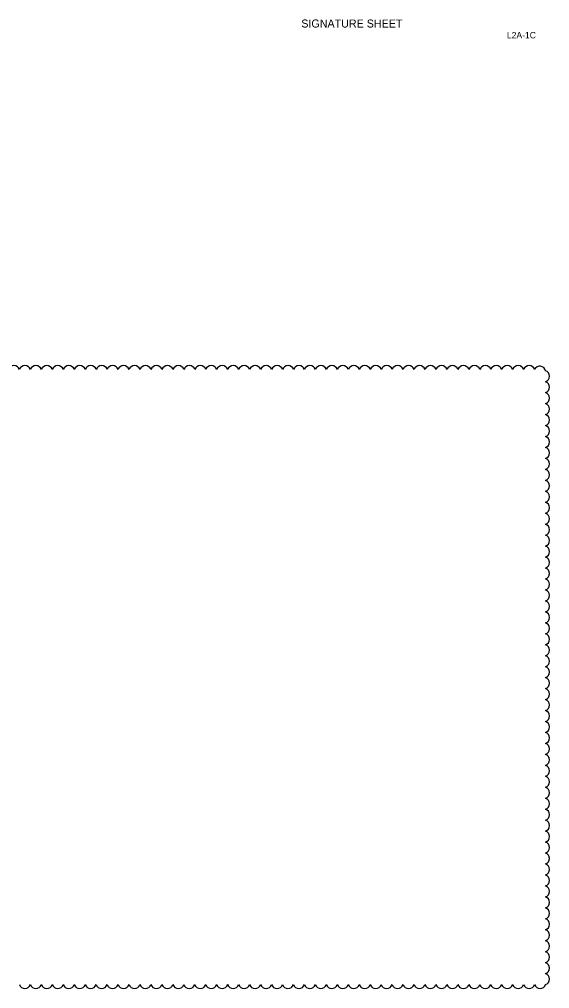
# Model space of a CAD drawing. Extents: x -811 to 10319, y -2309 to 9962.
# Drawn here: x -803.6 to -795.32, y -2244.74 to -2229.61 of the extents above; entities that cross this region are included whole.
import ezdxf

# ---------------------------------------------------------------- set-up
doc = ezdxf.new("R2010")
doc.units = 0
for name, color, linetype in [('PlotBorder_dp', 7, 'Continuous'), ('SheetLines_dp', 7, 'Continuous'), ('TextTitle', 7, 'Continuous')]:
    doc.layers.add(name, color=color, linetype=linetype)

msp = doc.modelspace()

# ---------------------------------------------------------------- linework, layer by layer
at = {"layer": 'TextTitle'}
for centre, radius, start, end in [((-803.684, -2235.106), 0.0897, 17.5, 162.5), ((-803.513, -2235.106), 0.0897, 17.5, 162.5), ((-803.342, -2235.106), 0.0897, 17.5, 162.5), ((-803.171, -2235.106), 0.0897, 17.5, 162.5), ((-803, -2235.106), 0.0897, 17.5, 162.5), ((-802.829, -2235.106), 0.0897, 17.5, 162.5), ((-802.657, -2235.106), 0.0897, 17.5, 162.5), ((-802.486, -2235.106), 0.0897, 17.5, 162.5), ((-802.315, -2235.106), 0.0897, 17.5, 162.5), ((-802.144, -2235.106), 0.0897, 17.5, 162.5), ((-801.973, -2235.106), 0.0897, 17.5, 162.5), ((-801.802, -2235.106), 0.0897, 17.5, 162.5), ((-801.631, -2235.106), 0.0897, 17.5, 162.5), ((-801.46, -2235.106), 0.0897, 17.5, 162.5), ((-801.288, -2235.106), 0.0897, 17.5, 162.5), ((-801.117, -2235.106), 0.0897, 17.5, 162.5), ((-800.946, -2235.106), 0.0897, 17.5, 162.5), ((-800.775, -2235.106), 0.0897, 17.5, 162.5), ((-800.604, -2235.106), 0.0897, 17.5, 162.5), ((-800.433, -2235.106), 0.0897, 17.5, 162.5), ((-800.262, -2235.106), 0.0897, 17.5, 162.5), ((-800.091, -2235.106), 0.0897, 17.5, 162.5), ((-799.919, -2235.106), 0.0897, 17.5, 162.5), ((-799.748, -2235.106), 0.0897, 17.5, 162.5), ((-799.577, -2235.106), 0.0897, 17.5, 162.5), ((-799.406, -2235.106), 0.0897, 17.5, 162.5), ((-799.235, -2235.106), 0.0897, 17.5, 162.5), ((-799.064, -2235.106), 0.0897, 17.5, 162.5), ((-798.893, -2235.106), 0.0897, 17.5, 162.5), ((-798.722, -2235.106), 0.0897, 17.5, 162.5), ((-798.551, -2235.106), 0.0897, 17.5, 162.5), ((-798.379, -2235.106), 0.0897, 17.5, 162.5), ((-798.208, -2235.106), 0.0897, 17.5, 162.5), ((-798.037, -2235.106), 0.0897, 17.5, 162.5), ((-797.866, -2235.106), 0.0897, 17.5, 162.5), ((-797.695, -2235.106), 0.0897, 17.5, 162.5), ((-797.524, -2235.106), 0.0897, 17.5, 162.5), ((-797.353, -2235.106), 0.0897, 17.5, 162.5), ((-797.182, -2235.106), 0.0897, 17.5, 162.5), ((-797.01, -2235.106), 0.0897, 17.5, 162.5), ((-796.839, -2235.106), 0.0897, 17.5, 162.5), ((-796.668, -2235.106), 0.0897, 17.5, 162.5), ((-796.497, -2235.106), 0.0897, 17.5, 162.5), ((-796.326, -2235.106), 0.0897, 17.5, 162.5), ((-796.155, -2235.106), 0.0897, 17.5, 162.5), ((-795.984, -2235.106), 0.0897, 17.5, 162.5), ((-795.813, -2235.106), 0.0897, 17.5, 162.5), ((-795.641, -2235.106), 0.0897, 17.5, 162.5), ((-795.474, -2235.115), 0.0896, 11.7454, 156.7454), ((-795.413, -2235.182), 0.0897, 287.5, 72.5), ((-795.413, -2235.353), 0.0897, 287.5, 72.5), ((-795.413, -2235.524), 0.0897, 287.5, 72.5), ((-795.413, -2235.695), 0.0897, 287.5, 72.5), ((-795.413, -2235.866), 0.0897, 287.5, 72.5), ((-795.413, -2236.038), 0.0897, 287.5, 72.5), ((-795.413, -2236.209), 0.0897, 287.5, 72.5), ((-795.413, -2236.38), 0.0897, 287.5, 72.5), ((-795.413, -2236.551), 0.0897, 287.5, 72.5), ((-795.413, -2236.722), 0.0897, 287.5, 72.5), ((-795.413, -2236.893), 0.0897, 287.5, 72.5), ((-795.413, -2237.064), 0.0897, 287.5, 72.5), ((-795.413, -2237.235), 0.0897, 287.5, 72.5), ((-795.413, -2237.407), 0.0897, 287.5, 72.5), ((-795.413, -2237.578), 0.0897, 287.5, 72.5), ((-795.413, -2237.749), 0.0897, 287.5, 72.5), ((-795.413, -2237.92), 0.0897, 287.5, 72.5), ((-795.413, -2238.091), 0.0897, 287.5, 72.5), ((-795.413, -2238.262), 0.0897, 287.5, 72.5), ((-795.413, -2238.433), 0.0897, 287.5, 72.5), ((-795.413, -2238.604), 0.0897, 287.5, 72.5), ((-795.413, -2238.776), 0.0897, 287.5, 72.5), ((-795.413, -2238.947), 0.0897, 287.5, 72.5), ((-795.413, -2239.118), 0.0897, 287.5, 72.5), ((-795.413, -2239.289), 0.0897, 287.5, 72.5), ((-795.413, -2239.46), 0.0897, 287.5, 72.5), ((-795.413, -2239.631), 0.0897, 287.5, 72.5), ((-795.413, -2239.802), 0.0897, 287.5, 72.5), ((-795.413, -2239.973), 0.0897, 287.5, 72.5), ((-795.413, -2240.144), 0.0897, 287.5, 72.5), ((-795.413, -2240.316), 0.0897, 287.5, 72.5), ((-795.413, -2240.487), 0.0897, 287.5, 72.5), ((-795.413, -2240.658), 0.0897, 287.5, 72.5), ((-795.413, -2240.829), 0.0897, 287.5, 72.5), ((-795.413, -2241), 0.0897, 287.5, 72.5), ((-795.413, -2241.171), 0.0897, 287.5, 72.5), ((-795.413, -2241.342), 0.0897, 287.5, 72.5), ((-795.413, -2241.513), 0.0897, 287.5, 72.5), ((-795.413, -2241.685), 0.0897, 287.5, 72.5), ((-795.413, -2241.856), 0.0897, 287.5, 72.5), ((-795.413, -2242.027), 0.0897, 287.5, 72.5), ((-795.413, -2242.198), 0.0897, 287.5, 72.5), ((-795.413, -2242.369), 0.0897, 287.5, 72.5), ((-795.413, -2242.54), 0.0897, 287.5, 72.5), ((-795.413, -2242.711), 0.0897, 287.5, 72.5), ((-795.413, -2242.882), 0.0897, 287.5, 72.5), ((-795.413, -2243.054), 0.0897, 287.5, 72.5), ((-795.413, -2243.225), 0.0897, 287.5, 72.5), ((-795.413, -2243.396), 0.0897, 287.5, 72.5), ((-795.413, -2243.567), 0.0897, 287.5, 72.5), ((-795.413, -2243.738), 0.0897, 287.5, 72.5), ((-795.413, -2243.909), 0.0897, 287.5, 72.5), ((-795.413, -2244.08), 0.0897, 287.5, 72.5), ((-795.413, -2244.251), 0.0897, 287.5, 72.5), ((-795.413, -2244.423), 0.0897, 287.5, 72.5), ((-795.413, -2244.594), 0.0897, 287.5, 72.5), ((-803.514, -2244.652), 0.0897, 197.5, 342.5), ((-803.343, -2244.652), 0.0897, 197.5, 342.5), ((-803.172, -2244.652), 0.0897, 197.5, 342.5), ((-803.001, -2244.652), 0.0897, 197.5, 342.5), ((-802.83, -2244.652), 0.0897, 197.5, 342.5), ((-802.658, -2244.652), 0.0897, 197.5, 342.5), ((-802.487, -2244.652), 0.0897, 197.5, 342.5), ((-802.316, -2244.652), 0.0897, 197.5, 342.5), ((-802.145, -2244.652), 0.0897, 197.5, 342.5), ((-801.974, -2244.652), 0.0897, 197.5, 342.5), ((-801.803, -2244.652), 0.0897, 197.5, 342.5), ((-801.632, -2244.652), 0.0897, 197.5, 342.5), ((-801.461, -2244.652), 0.0897, 197.5, 342.5), ((-801.289, -2244.652), 0.0897, 197.5, 342.5), ((-801.118, -2244.652), 0.0897, 197.5, 342.5), ((-800.947, -2244.652), 0.0897, 197.5, 342.5), ((-800.776, -2244.652), 0.0897, 197.5, 342.5), ((-800.605, -2244.652), 0.0897, 197.5, 342.5), ((-800.434, -2244.652), 0.0897, 197.5, 342.5), ((-800.263, -2244.652), 0.0897, 197.5, 342.5), ((-800.092, -2244.652), 0.0897, 197.5, 342.5), ((-799.921, -2244.652), 0.0897, 197.5, 342.5), ((-799.749, -2244.652), 0.0897, 197.5, 342.5), ((-799.578, -2244.652), 0.0897, 197.5, 342.5), ((-799.407, -2244.652), 0.0897, 197.5, 342.5), ((-799.236, -2244.652), 0.0897, 197.5, 342.5), ((-799.065, -2244.652), 0.0897, 197.5, 342.5), ((-798.894, -2244.652), 0.0897, 197.5, 342.5), ((-798.723, -2244.652), 0.0897, 197.5, 342.5), ((-798.552, -2244.652), 0.0897, 197.5, 342.5), ((-798.38, -2244.652), 0.0897, 197.5, 342.5), ((-798.209, -2244.652), 0.0897, 197.5, 342.5), ((-798.038, -2244.652), 0.0897, 197.5, 342.5), ((-797.867, -2244.652), 0.0897, 197.5, 342.5), ((-797.696, -2244.652), 0.0897, 197.5, 342.5), ((-797.525, -2244.652), 0.0897, 197.5, 342.5), ((-797.354, -2244.652), 0.0897, 197.5, 342.5), ((-797.183, -2244.652), 0.0897, 197.5, 342.5), ((-797.011, -2244.652), 0.0897, 197.5, 342.5), ((-796.84, -2244.652), 0.0897, 197.5, 342.5), ((-796.669, -2244.652), 0.0897, 197.5, 342.5), ((-796.498, -2244.652), 0.0897, 197.5, 342.5), ((-796.327, -2244.652), 0.0897, 197.5, 342.5), ((-796.156, -2244.652), 0.0897, 197.5, 342.5), ((-795.985, -2244.652), 0.0897, 197.5, 342.5), ((-795.814, -2244.652), 0.0897, 197.5, 342.5), ((-795.642, -2244.652), 0.0897, 197.5, 342.5), ((-795.471, -2244.652), 0.0897, 197.5, 342.5)]:
    msp.add_arc(centre, radius, start, end, dxfattribs=at)

# ---------------------------------------------------------------- texts
at = {"layer": 'PlotBorder_dp'}
msp.add_text('       SIGNATURE SHEET         ', height=0.125, dxfattribs=at).set_placement((-799.524, -2229.739))
at = {"layer": 'SheetLines_dp'}
msp.add_text('L2A-1C', height=0.1, dxfattribs=at).set_placement((-795.99, -2229.908))

doc.saveas('drawing.dxf')
